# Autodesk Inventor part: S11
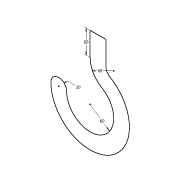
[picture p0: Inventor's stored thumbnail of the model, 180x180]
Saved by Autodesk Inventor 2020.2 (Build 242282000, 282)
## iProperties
Created: 2013-12
Part Number: S11
Material: Ogólny
Document SubType Name: Modeling
Designer: F.Stasiak
Density: 1 g/cm^3
Appearance: Domyślna
Manager: www.cadconsulting.pl
Company: Fabian Stasiak CAD Consulting
Author: F.Stasiak
Subject: Zbiór ćwiczeń. Autodesk Inventor 2020. Kurs podstawowy
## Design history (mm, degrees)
sketch "Szkic1"
  geometry: L1 (0, 163.923)-(0, 103.923); L2 (40, 103.923)-(40, 163.923); L3 (40, 163.923)-(0, 163.923); A1 r 60 centre (60, 103.923) between (0, 103.923) and (30, 51.962); A2 r 60 centre (0, 0) between (-60, 0) and (30, 51.962); A3 r 20 centre (-80, 0) between (-60, 0) and (-100, 0); A4 r 100 centre (0, 0) between (-100, 0) and (50, 86.603); A5 r 20 centre (60, 103.923) between (40, 103.923) and (50, 86.603); 1 further point
  constraints: 10 point on circle, 6 end point, 6 tangent, 5 centre point, 2 coincident, 1 concentric, 1 horizontal alignment, 1 parallel, 1 perpendicular, 1 point on line, 1 vertical
  dimensions: "d0" = 60 radius of A2; "d1" = 20 radius of A3; "d2" = 60 radius of A1; "d3" = 60 distance of L1.start L1.end
